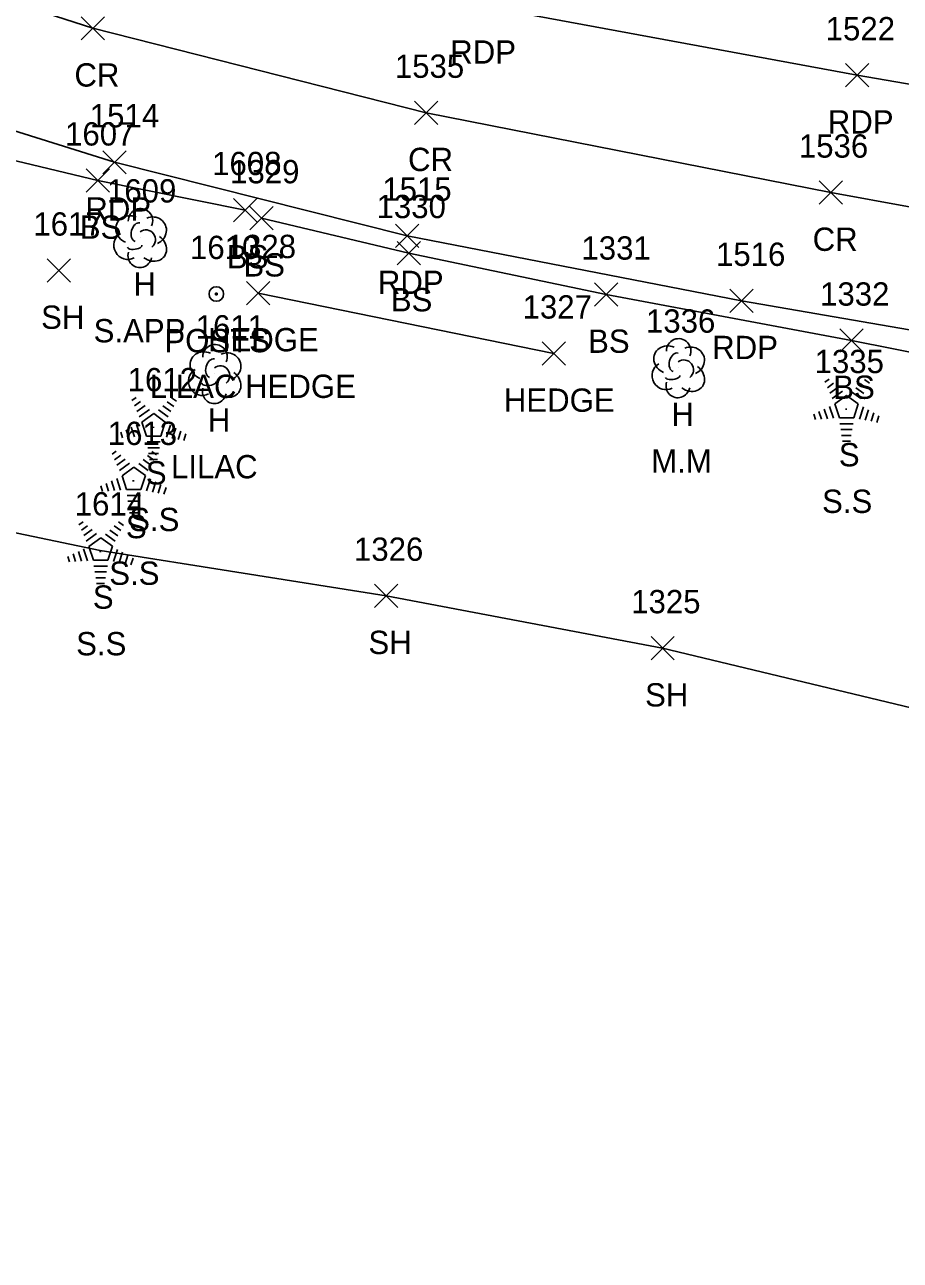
# Model space of a CAD drawing. Extents: x 1616726 to 1619875, y 273782 to 276557.
# Drawn here: x 1616883.5 to 1616958.6, y 276105.3 to 276211.4 of the extents above; entities that cross this region are included whole.
import ezdxf

# ---------------------------------------------------------------- set-up
doc = ezdxf.new("R2010")
doc.units = 0
for name, color, linetype in [('L_A', 7, 'Continuous'), ('L_C', 7, 'Continuous'), ('L_I', 7, 'Continuous'), ('L_TIC', 7, 'Continuous'), ('LAHR', 7, 'Continuous'), ('LELB', 7, 'Continuous'), ('LPST', 7, 'Continuous'), ('LSOGP', 7, 'Continuous'), ('LTC', 7, 'Continuous'), ('LTD', 7, 'Continuous'), ('P_A', 7, 'Continuous'), ('P_I', 7, 'Continuous'), ('P_TIC', 7, 'Continuous'), ('PET', 7, 'Continuous'), ('PRC', 7, 'Continuous')]:
    doc.layers.add(name, color=color, linetype=linetype)

msp = doc.modelspace()

# ---------------------------------------------------------------- linework, layer by layer
at = {"layer": 'L_TIC'}
for points in [[(1616888.75, 276197.01), (1616890.75, 276199.01)], [(1616890.75, 276197.01), (1616888.75, 276199.01)], [(1616901.37, 276194.47), (1616903.37, 276196.47)], [(1616903.37, 276194.47), (1616901.37, 276196.47)], [(1616902.79, 276193.77), (1616904.79, 276195.77)], [(1616904.79, 276193.77), (1616902.79, 276195.77)], [(1616915.44, 276190.78), (1616917.44, 276192.78)], [(1616917.44, 276190.78), (1616915.44, 276192.78)], [(1616885.38, 276189.28), (1616887.38, 276191.28)], [(1616887.38, 276189.28), (1616885.38, 276191.28)], [(1616902.49, 276187.35), (1616904.49, 276189.35)], [(1616904.49, 276187.35), (1616902.49, 276189.35)], [(1616932.37, 276187.22), (1616934.37, 276189.22)], [(1616934.37, 276187.22), (1616932.37, 276189.22)], [(1616953.41, 276183.27), (1616955.41, 276185.27)], [(1616955.41, 276183.27), (1616953.41, 276185.27)], [(1616927.88, 276182.16), (1616929.88, 276184.16)], [(1616929.88, 276182.16), (1616927.88, 276184.16)], [(1616913.47, 276161.37), (1616915.47, 276163.37)], [(1616915.47, 276161.37), (1616913.47, 276163.37)], [(1616937.21, 276156.87), (1616939.21, 276158.87)], [(1616939.21, 276156.87), (1616937.21, 276158.87)]]:
    msp.add_lwpolyline(points, dxfattribs=at)
at = {"layer": 'LAHR'}
msp.add_lwpolyline([(1616928.88, 276183.16), (1616903.49, 276188.35)], dxfattribs=at)
at = {"layer": 'LELB'}
for points in [[(1616860.43, 276188.06), (1616870.75, 276202.55), (1616889.75, 276198.01), (1616902.37, 276195.47)], [(1616903.79, 276194.77), (1616916.44, 276191.78), (1616933.37, 276188.22), (1616954.41, 276184.27), (1616980.35, 276179.12)]]:
    msp.add_lwpolyline(points, dxfattribs=at)
at = {"layer": 'LPST'}
for radius in [0.625, 0.0833]:
    msp.add_circle((1616899.91, 276188.27), radius, dxfattribs=at)
at = {"layer": 'LSOGP'}
msp.add_lwpolyline([(1616868.68, 276170.68), (1616889.93, 276166.26), (1616914.47, 276162.37), (1616938.21, 276157.87), (1616961.67, 276152.23), (1616975.36, 276145.27), (1617009.96, 276137.1), (1617027.24, 276138.17), (1617037.14, 276137.25), (1617054.32, 276131.49), (1617066.36, 276127.08), (1617078.89, 276126), (1617091.1, 276125.93), (1617113.14, 276115.76), (1617128.25, 276113.28), (1617136.7, 276109.65), (1617140.03, 276109.3), (1617154.79, 276105.34)], dxfattribs=at)
at = {"layer": 'LTC'}
for p, q in [((1616952.14, 276180.69), (1616952.49, 276180.95)), ((1616952.35, 276180.22), (1616952.87, 276180.61)), ((1616952.56, 276179.76), (1616953.26, 276180.27)), ((1616954.79, 276180.23), (1616955.47, 276179.74)), ((1616955.16, 276180.58), (1616955.71, 276180.18)), ((1616955.53, 276180.93), (1616955.95, 276180.62)), ((1616892.67, 276179.13), (1616893.03, 276179.38)), ((1616896.07, 276179.37), (1616896.49, 276179.06)), ((1616952.76, 276179.29), (1616953.64, 276179.93)), ((1616952.99, 276178.84), (1616954, 276179.57)), ((1616954, 276179.57), (1616955, 276178.85)), ((1616954.42, 276179.88), (1616955.23, 276179.3)), ((1616892.88, 276178.66), (1616893.41, 276179.05)), ((1616893.09, 276178.2), (1616893.79, 276178.71)), ((1616893.3, 276177.73), (1616894.18, 276178.37)), ((1616893.52, 276177.27), (1616894.54, 276178.01)), ((1616894.54, 276178.01), (1616895.53, 276177.28)), ((1616894.96, 276178.32), (1616895.77, 276177.73)), ((1616895.33, 276178.67), (1616896.01, 276178.18)), ((1616895.7, 276179.02), (1616896.25, 276178.62)), ((1616951.62, 276178.18), (1616951.84, 276177.53)), ((1616952.08, 276178.4), (1616952.35, 276177.57)), ((1616952.53, 276178.62), (1616952.87, 276177.6)), ((1616952.99, 276178.84), (1616953.38, 276177.64)), ((1616955, 276178.85), (1616954.61, 276177.64)), ((1616955.44, 276178.58), (1616955.1, 276177.54)), ((1616955.88, 276178.32), (1616955.59, 276177.44)), ((1616956.32, 276178.07), (1616956.09, 276177.35)), ((1616893.07, 276177.06), (1616893.4, 276176.04)), ((1616893.52, 276177.27), (1616893.91, 276176.08)), ((1616895.53, 276177.28), (1616895.14, 276176.08)), ((1616895.97, 276177.01), (1616895.63, 276175.97)), ((1616951.17, 276177.97), (1616951.32, 276177.5)), ((1616954.61, 276177.64), (1616953.38, 276177.64)), ((1616954.57, 276177.14), (1616953.42, 276177.14)), ((1616956.77, 276177.82), (1616956.58, 276177.25)), ((1616891.7, 276176.41), (1616891.86, 276175.94)), ((1616892.16, 276176.62), (1616892.37, 276175.97)), ((1616892.61, 276176.84), (1616892.89, 276176)), ((1616895.14, 276176.08), (1616893.91, 276176.08)), ((1616896.42, 276176.76), (1616896.13, 276175.88)), ((1616896.86, 276176.51), (1616896.62, 276175.78)), ((1616897.3, 276176.26), (1616897.12, 276175.69)), ((1616954.48, 276176.64), (1616953.5, 276176.64)), ((1616954.4, 276176.14), (1616953.57, 276176.14)), ((1616895.1, 276175.58), (1616893.96, 276175.58)), ((1616895.02, 276175.08), (1616894.03, 276175.08)), ((1616954.32, 276175.64), (1616953.64, 276175.64)), ((1616890.96, 276174.52), (1616891.32, 276174.78)), ((1616891.17, 276174.05), (1616891.7, 276174.44)), ((1616891.38, 276173.59), (1616892.08, 276174.1)), ((1616891.59, 276173.12), (1616892.47, 276173.76)), ((1616893.62, 276174.06), (1616894.3, 276173.57)), ((1616893.99, 276174.41), (1616894.54, 276174.01)), ((1616894.94, 276174.58), (1616894.1, 276174.58)), ((1616894.85, 276174.08), (1616894.18, 276174.08)), ((1616894.36, 276174.76), (1616894.78, 276174.46)), ((1616891.82, 276172.67), (1616892.83, 276173.4)), ((1616892.83, 276173.4), (1616893.82, 276172.68)), ((1616893.25, 276173.72), (1616894.06, 276173.13)), ((1616889.99, 276171.8), (1616890.15, 276171.33)), ((1616890.45, 276172.02), (1616890.66, 276171.36)), ((1616890.91, 276172.23), (1616891.18, 276171.4)), ((1616891.36, 276172.45), (1616891.69, 276171.43)), ((1616891.82, 276172.67), (1616892.2, 276171.48)), ((1616893.82, 276172.68), (1616893.43, 276171.48)), ((1616894.26, 276172.41), (1616893.92, 276171.37)), ((1616894.71, 276172.16), (1616894.42, 276171.27)), ((1616895.15, 276171.91), (1616894.91, 276171.18)), ((1616895.59, 276171.66), (1616895.41, 276171.08)), ((1616893.43, 276171.48), (1616892.2, 276171.48)), ((1616893.39, 276170.98), (1616892.25, 276170.98)), ((1616893.31, 276170.48), (1616892.32, 276170.48)), ((1616893.23, 276169.98), (1616892.4, 276169.98)), ((1616888.12, 276168.47), (1616888.48, 276168.72)), ((1616891.52, 276168.71), (1616891.94, 276168.4)), ((1616893.14, 276169.48), (1616892.47, 276169.48)), ((1616888.33, 276168), (1616888.86, 276168.38)), ((1616888.54, 276167.53), (1616889.25, 276168.05)), ((1616888.75, 276167.07), (1616889.63, 276167.71)), ((1616890.41, 276167.66), (1616891.22, 276167.07)), ((1616890.78, 276168.01), (1616891.46, 276167.52)), ((1616891.15, 276168.36), (1616891.7, 276167.96)), ((1616888.52, 276166.39), (1616888.85, 276165.38)), ((1616888.98, 276166.61), (1616889.99, 276167.35)), ((1616888.98, 276166.61), (1616889.36, 276165.42)), ((1616889.99, 276167.35), (1616890.99, 276166.62)), ((1616890.99, 276166.62), (1616890.6, 276165.42)), ((1616891.42, 276166.35), (1616891.09, 276165.31)), ((1616887.16, 276165.75), (1616887.31, 276165.28)), ((1616887.61, 276165.96), (1616887.82, 276165.31)), ((1616888.07, 276166.18), (1616888.34, 276165.34)), ((1616890.6, 276165.42), (1616889.36, 276165.42)), ((1616891.87, 276166.1), (1616891.58, 276165.22)), ((1616892.31, 276165.85), (1616892.08, 276165.12)), ((1616892.76, 276165.6), (1616892.57, 276165.03)), ((1616890.56, 276164.92), (1616889.41, 276164.92)), ((1616890.47, 276164.42), (1616889.48, 276164.42)), ((1616890.39, 276163.92), (1616889.56, 276163.92)), ((1616890.31, 276163.42), (1616889.63, 276163.42))]:
    msp.add_line(p, q, dxfattribs=at)
at = {"layer": 'LTD'}
for p, q in [((1616893.36, 276193.12), (1616893.36, 276193.12)), ((1616893.36, 276193.12), (1616893.36, 276193.12)), ((1616899.74, 276181.45), (1616899.74, 276181.45)), ((1616899.74, 276181.45), (1616899.74, 276181.45)), ((1616939.53, 276181.95), (1616939.53, 276181.95)), ((1616939.53, 276181.95), (1616939.53, 276181.95))]:
    msp.add_line(p, q, dxfattribs=at)
for centre in [(1616893.4, 276194.55), (1616939.58, 276183.39), (1616899.79, 276182.88)]:
    msp.add_arc(centre, 1.05, 335.5272, 180.9563, dxfattribs=at)
for centre, major_axis, ratio, start_param, end_param in [((1616892.57, 276193.79), (1.21, -0.51), 0.895232, 1.570796, 4.712389), ((1616894.4, 276193.7), (-1.14, -0.48), 0.949671, 1.570796, 4.712389), ((1616893.15, 276193.58), (-0.208, -0.792), 0.645439, 3.141593, 6.283185), ((1616892.27, 276192.41), (0.58, -1.04), 0.959034, 3.141593, 6.283185), ((1616893.86, 276192.95), (-0.5, 0.667), 0.989748, 3.141593, 6.283185), ((1616894.36, 276192.29), (-1.09, 0.79), 0.841452, 1.570796, 4.712389), ((1616893.36, 276191.62), (0.26, 1.06), 0.942809, 1.570796, 4.712389), ((1616892.9, 276192.37), (-0.625, -0.083), 0.423636, 0, 3.141593), ((1616898.95, 276182.11), (1.21, -0.51), 0.895232, 1.570796, 4.712389), ((1616900.79, 276182.03), (-1.14, -0.48), 0.949671, 1.570796, 4.712389), ((1616938.74, 276182.62), (1.21, -0.51), 0.895232, 1.570796, 4.712389), ((1616940.57, 276182.53), (-1.14, -0.48), 0.949671, 1.570796, 4.712389), ((1616899.54, 276181.9), (-0.208, -0.792), 0.645439, 3.141593, 6.283185), ((1616938.45, 276181.24), (0.58, -1.04), 0.959034, 3.141593, 6.283185), ((1616939.32, 276182.41), (-0.208, -0.792), 0.645439, 3.141593, 6.283185), ((1616940.03, 276181.78), (-0.5, 0.667), 0.989748, 3.141593, 6.283185), ((1616898.66, 276180.74), (0.58, -1.04), 0.959034, 3.141593, 6.283185), ((1616900.24, 276181.28), (-0.5, 0.667), 0.989748, 3.141593, 6.283185), ((1616900.74, 276180.61), (-1.09, 0.79), 0.841452, 1.570796, 4.712389), ((1616939.07, 276181.2), (-0.625, -0.083), 0.423636, 0, 3.141593), ((1616940.53, 276181.12), (-1.09, 0.79), 0.841452, 1.570796, 4.712389), ((1616899.75, 276179.95), (0.26, 1.06), 0.942809, 1.570796, 4.712389), ((1616899.29, 276180.69), (-0.625, -0.083), 0.423636, 0, 3.141593), ((1616939.53, 276180.45), (0.26, 1.06), 0.942809, 1.570796, 4.712389)]:
    msp.add_ellipse(centre, major_axis=major_axis, ratio=ratio, start_param=start_param, end_param=end_param, dxfattribs=at)
at = {"layer": 'P_TIC'}
for points in [[(1616888.3, 276210.07), (1616890.3, 276212.07)], [(1616890.3, 276210.07), (1616888.3, 276212.07)], [(1616953.9, 276206.04), (1616955.9, 276208.04)], [(1616955.9, 276206.04), (1616953.9, 276208.04)], [(1616916.92, 276202.82), (1616918.92, 276204.82)], [(1616918.92, 276202.82), (1616916.92, 276204.82)], [(1616890.18, 276198.57), (1616892.18, 276200.57)], [(1616892.18, 276198.57), (1616890.18, 276200.57)], [(1616951.65, 276195.97), (1616953.65, 276197.97)], [(1616953.65, 276195.97), (1616951.65, 276197.97)], [(1616915.28, 276192.27), (1616917.28, 276194.27)], [(1616917.28, 276192.27), (1616915.28, 276194.27)], [(1616943.97, 276186.68), (1616945.97, 276188.68)], [(1616945.97, 276186.68), (1616943.97, 276188.68)]]:
    msp.add_lwpolyline(points, dxfattribs=at)
at = {"layer": 'PET'}
for points in [[(1616988.41, 276201.28), (1616954.9, 276207.04), (1616922.49, 276213.04), (1616897.19, 276219.39), (1616868.83, 276227.99), (1616843.51, 276236.97), (1616821.5, 276246.17), (1616797.48, 276256.89), (1616777.93, 276266.16)], [(1616769.24, 276246.91), (1616790.9, 276236.62), (1616808.6, 276228.19), (1616836.41, 276217.31), (1616861.69, 276208.81), (1616891.18, 276199.57), (1616916.28, 276193.27), (1616944.97, 276187.68), (1616979.27, 276181.76), (1617009.13, 276177.18), (1617040.1, 276173.73), (1617058.02, 276171.48)]]:
    msp.add_lwpolyline(points, dxfattribs=at)
at = {"layer": 'PRC'}
msp.add_lwpolyline([(1616773.7, 276256.44), (1616798, 276244.91), (1616831.43, 276231.02), (1616858.04, 276221.16), (1616889.3, 276211.07), (1616917.92, 276203.82), (1616952.65, 276196.97), (1616987.1, 276190.69)], dxfattribs=at)

# ---------------------------------------------------------------- texts
at = {"layer": 'L_A'}
for s, p in [('BS', (1616888.19, 276193.01)), ('BS', (1616900.81, 276190.47)), ('BS', (1616902.23, 276189.77)), ('H', (1616892.79, 276188.12)), ('BS', (1616914.88, 276186.78)), ('SH', (1616884.87, 276185.28)), ('POSTS', (1616895.45, 276183.27)), ('HEDGE', (1616899.19, 276183.35)), ('BS', (1616931.81, 276183.22)), ('BS', (1616952.85, 276179.27)), ('HEDGE', (1616924.58, 276178.16)), ('H', (1616899.18, 276176.45)), ('H', (1616938.96, 276176.95)), ('S', (1616953.33, 276173.48)), ('S', (1616893.86, 276171.92)), ('S', (1616892.15, 276167.31)), ('S', (1616889.31, 276161.26)), ('SH', (1616912.96, 276157.37)), ('SH', (1616936.7, 276152.87))]:
    msp.add_text(s, height=2, dxfattribs=at).set_placement(p)
at = {"layer": 'L_C'}
for s, p in [('S.APP', (1616889.38, 276184.12)), ('LILAC HEDGE', (1616894.2, 276179.35)), ('M.M', (1616937.23, 276172.95)), ('LILAC', (1616896.02, 276172.45)), ('S.S', (1616951.89, 276169.48)), ('S.S', (1616892.43, 276167.92)), ('S.S', (1616890.72, 276163.31)), ('S.S', (1616887.88, 276157.26))]:
    msp.add_text(s, height=2, dxfattribs=at).set_placement(p)
at = {"layer": 'L_I'}
for s, p in [('1607', (1616886.93, 276201.01)), ('1608', (1616899.55, 276198.47)), ('1329', (1616901.09, 276197.77)), ('1609', (1616890.53, 276196.12)), ('1330', (1616913.66, 276194.78)), ('1617', (1616884.21, 276193.28)), ('1610', (1616897.65, 276191.27)), ('1328', (1616900.8, 276191.35)), ('1331', (1616931.24, 276191.22)), ('1332', (1616951.72, 276187.27)), ('1327', (1616926.19, 276186.16)), ('1336', (1616936.78, 276184.95)), ('1611', (1616898.14, 276184.45)), ('1335', (1616951.25, 276181.48)), ('1612', (1616892.3, 276179.92)), ('1613', (1616890.59, 276175.31)), ('1614', (1616887.76, 276169.26)), ('1326', (1616911.72, 276165.37)), ('1325', (1616935.51, 276160.87))]:
    msp.add_text(s, height=2, dxfattribs=at).set_placement(p)
at = {"layer": 'LTC'}
for p in [(1616953.88, 276178.58), (1616894.42, 276177.02), (1616892.71, 276172.42), (1616889.87, 276166.36)]:
    msp.add_text('.', height=1.04, rotation=270, dxfattribs=at).set_placement(p)
at = {"layer": 'P_A'}
for s, p in [('RDP', (1616919.98, 276208.04)), ('CR', (1616887.73, 276206.07)), ('RDP', (1616952.38, 276202.04)), ('CR', (1616916.36, 276198.82)), ('RDP', (1616888.67, 276194.57)), ('CR', (1616951.08, 276191.97)), ('RDP', (1616913.77, 276188.27)), ('RDP', (1616942.46, 276182.68))]:
    msp.add_text(s, height=2, dxfattribs=at).set_placement(p)
at = {"layer": 'P_I'}
for s, p in [('1522', (1616952.2, 276210.04)), ('1535', (1616915.23, 276206.82)), ('1514', (1616889.05, 276202.57)), ('1536', (1616949.9, 276199.97)), ('1515', (1616914.15, 276196.27)), ('1516', (1616942.79, 276190.68))]:
    msp.add_text(s, height=2, dxfattribs=at).set_placement(p)

doc.saveas('drawing.dxf')
